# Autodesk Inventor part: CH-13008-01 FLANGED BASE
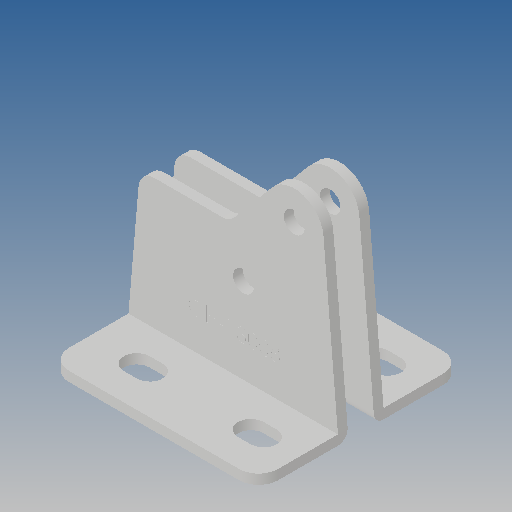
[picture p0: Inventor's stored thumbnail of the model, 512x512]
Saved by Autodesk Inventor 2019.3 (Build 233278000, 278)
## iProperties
Created: 2012-09
Part Number: CH-13008-01 FLANGED BASE
Material: Ogólny
Document SubType Name: Modeling
Designer: CADENGINEERING4
Density: 1 g/cm^3
Appearance: Domyślna
Author: CADENGINEERING4
Revision Number: ÈÎºÎ
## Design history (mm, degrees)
feature "ÇÐ³ý-À­Éì2"
feature "ÊµÌå-ÒÆ¶¯_¸´ÖÆ1"
node "Bryła1"
node "Bryła2"
